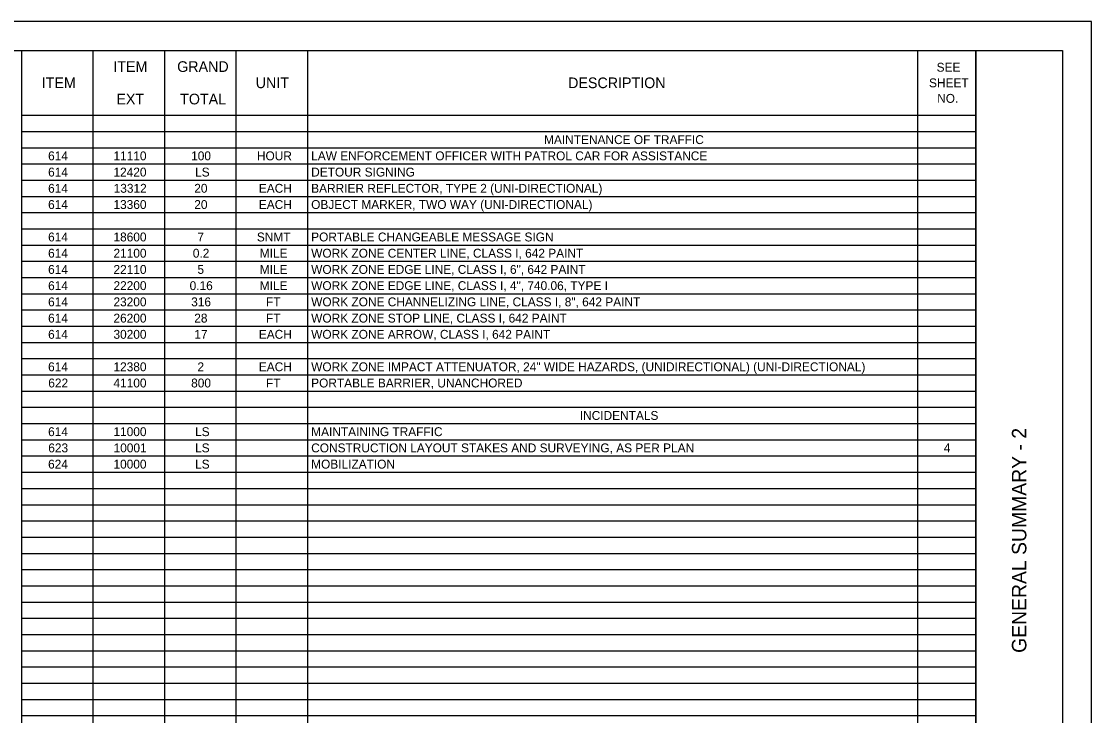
# Model space of a CAD drawing. Extents: x 0 to 34, y 0 to 22.
# Drawn here: x 15.54 to 34, y 10.02 to 22 of the extents above; entities that cross this region are included whole.
import ezdxf

# ---------------------------------------------------------------- set-up
doc = ezdxf.new("R2010")
doc.units = 0
for name, color, linetype in [('SH_Border', 7, 'Continuous'), ('SH_Cut_Line', 7, 'Continuous'), ('SH_Data', 7, 'Continuous'), ('SH_Text', 7, 'Continuous')]:
    doc.layers.add(name, color=color, linetype=linetype)

msp = doc.modelspace()

# ---------------------------------------------------------------- linework, layer by layer
at = {"layer": 'SH_Border'}
msp.add_line((32, 0.5), (32, 21.5), dxfattribs=at)
msp.add_lwpolyline([(1.5, 21.5), (33.5, 21.5), (33.5, 0.5), (1.5, 0.5)], close=True, dxfattribs=at)
at = {"layer": 'SH_Cut_Line'}
msp.add_lwpolyline([(0, 0), (34, 0), (34, 22), (0, 22)], close=True, dxfattribs=at)
at = {"layer": 'SH_Text'}
for p, q in [((15.535, 21.5), (18.003, 21.5)), ((15.535, 21.5), (15.535, 21.22)), ((16.769, 21.5), (16.769, 21.22)), ((18.003, 21.5), (19.237, 21.5)), ((18.003, 21.5), (18.003, 21.22)), ((19.237, 21.5), (32, 21.5)), ((19.237, 21.5), (19.237, 21.22)), ((20.471, 21.5), (20.471, 21.22)), ((30.997, 21.5), (30.997, 21.22)), ((32, 21.5), (32, 21.22)), ((15.535, 21.22), (15.535, 20.94)), ((16.769, 21.22), (16.769, 20.94)), ((18.003, 21.22), (18.003, 20.94)), ((19.237, 21.22), (19.237, 20.94)), ((20.471, 21.22), (20.471, 20.94)), ((30.997, 21.22), (30.997, 20.94)), ((32, 21.22), (32, 20.94)), ((15.535, 20.94), (15.535, 20.66)), ((16.769, 20.94), (16.769, 20.66)), ((18.003, 20.94), (18.003, 20.66)), ((19.237, 20.94), (19.237, 20.66)), ((20.471, 20.94), (20.471, 20.66)), ((30.997, 20.94), (30.997, 20.66)), ((32, 20.94), (32, 20.66)), ((15.535, 20.66), (15.535, 20.38)), ((16.769, 20.66), (16.769, 20.38)), ((18.003, 20.66), (18.003, 20.38)), ((19.237, 20.66), (19.237, 20.38)), ((20.471, 20.66), (20.471, 20.38)), ((30.997, 20.66), (30.997, 20.38)), ((32, 20.66), (32, 20.38)), ((15.535, 20.38), (18.003, 20.38)), ((15.535, 20.38), (15.535, 20.1)), ((16.769, 20.38), (16.769, 20.1)), ((18.003, 20.38), (19.237, 20.38)), ((18.003, 20.38), (18.003, 20.1)), ((19.237, 20.38), (32, 20.38)), ((19.237, 20.38), (19.237, 20.1)), ((20.471, 20.38), (20.471, 20.1)), ((30.997, 20.38), (30.997, 20.1)), ((32, 20.38), (32, 20.1)), ((15.535, 20.1), (18.003, 20.1)), ((15.535, 20.1), (15.535, 18.7)), ((16.769, 20.1), (16.769, 18.7)), ((18.003, 20.1), (19.237, 20.1)), ((18.003, 20.1), (18.003, 18.7)), ((19.237, 20.1), (32, 20.1)), ((19.237, 20.1), (19.237, 18.7)), ((20.471, 20.1), (20.471, 18.7)), ((30.997, 20.1), (30.997, 18.7)), ((32, 20.1), (32, 18.7)), ((15.535, 19.82), (18.003, 19.82)), ((18.003, 19.82), (19.237, 19.82)), ((19.237, 19.82), (32, 19.82)), ((15.535, 19.54), (18.003, 19.54)), ((18.003, 19.54), (19.237, 19.54)), ((19.237, 19.54), (32, 19.54)), ((15.535, 19.26), (18.003, 19.26)), ((18.003, 19.26), (19.237, 19.26)), ((19.237, 19.26), (32, 19.26)), ((15.535, 18.98), (18.003, 18.98)), ((18.003, 18.98), (19.237, 18.98)), ((19.237, 18.98), (32, 18.98)), ((15.535, 18.7), (18.003, 18.7)), ((15.535, 18.7), (15.535, 18.14)), ((16.769, 18.7), (16.769, 18.14)), ((18.003, 18.7), (19.237, 18.7)), ((18.003, 18.7), (18.003, 18.14)), ((19.237, 18.7), (32, 18.7)), ((19.237, 18.7), (19.237, 18.14)), ((20.471, 18.7), (20.471, 18.14)), ((30.997, 18.7), (30.997, 18.14)), ((32, 18.7), (32, 18.14)), ((15.535, 18.42), (18.003, 18.42)), ((18.003, 18.42), (19.237, 18.42)), ((19.237, 18.42), (32, 18.42)), ((15.535, 18.14), (18.003, 18.14)), ((15.535, 18.14), (15.535, 17.86)), ((16.769, 18.14), (16.769, 17.86)), ((18.003, 18.14), (19.237, 18.14)), ((18.003, 18.14), (18.003, 17.86)), ((19.237, 18.14), (32, 18.14)), ((19.237, 18.14), (19.237, 17.86)), ((20.471, 18.14), (20.471, 17.86)), ((30.997, 18.14), (30.997, 17.86)), ((32, 18.14), (32, 17.86)), ((15.535, 17.86), (18.003, 17.86)), ((15.535, 17.86), (15.535, 17.58)), ((16.769, 17.86), (16.769, 17.58)), ((18.003, 17.86), (19.237, 17.86)), ((18.003, 17.86), (18.003, 17.58)), ((19.237, 17.86), (32, 17.86)), ((19.237, 17.86), (19.237, 17.58)), ((20.471, 17.86), (20.471, 17.58)), ((30.997, 17.86), (30.997, 17.58)), ((32, 17.86), (32, 17.58)), ((15.535, 17.58), (18.003, 17.58)), ((15.535, 17.58), (15.535, 17.3)), ((16.769, 17.58), (16.769, 17.3)), ((18.003, 17.58), (19.237, 17.58)), ((18.003, 17.58), (18.003, 17.3)), ((19.237, 17.58), (32, 17.58)), ((19.237, 17.58), (19.237, 17.3)), ((20.471, 17.58), (20.471, 17.3)), ((30.997, 17.58), (30.997, 17.3)), ((32, 17.58), (32, 17.3)), ((15.535, 17.3), (18.003, 17.3)), ((15.535, 17.3), (15.535, 17.02)), ((16.769, 17.3), (16.769, 17.02)), ((18.003, 17.3), (19.237, 17.3)), ((18.003, 17.3), (18.003, 17.02)), ((19.237, 17.3), (32, 17.3)), ((19.237, 17.3), (19.237, 17.02)), ((20.471, 17.3), (20.471, 17.02)), ((30.997, 17.3), (30.997, 17.02)), ((32, 17.3), (32, 17.02)), ((15.535, 17.02), (18.003, 17.02)), ((15.535, 17.02), (15.535, 16.74)), ((16.769, 17.02), (16.769, 16.74)), ((18.003, 17.02), (19.237, 17.02)), ((18.003, 17.02), (18.003, 16.74)), ((19.237, 17.02), (32, 17.02)), ((19.237, 17.02), (19.237, 16.74)), ((20.471, 17.02), (20.471, 16.74)), ((30.997, 17.02), (30.997, 16.74)), ((32, 17.02), (32, 16.74)), ((15.535, 16.74), (18.003, 16.74)), ((15.535, 16.74), (15.535, 16.18)), ((16.769, 16.74), (16.769, 16.18)), ((18.003, 16.74), (19.237, 16.74)), ((18.003, 16.74), (18.003, 16.18)), ((19.237, 16.74), (32, 16.74)), ((19.237, 16.74), (19.237, 16.18)), ((20.471, 16.74), (20.471, 16.18)), ((30.997, 16.74), (30.997, 16.18)), ((32, 16.74), (32, 16.18)), ((15.535, 16.46), (18.003, 16.46)), ((18.003, 16.46), (19.237, 16.46)), ((19.237, 16.46), (32, 16.46)), ((15.535, 16.18), (18.003, 16.18)), ((15.535, 16.18), (15.535, 15.9)), ((16.769, 16.18), (16.769, 15.9)), ((18.003, 16.18), (19.237, 16.18)), ((18.003, 16.18), (18.003, 15.9)), ((19.237, 16.18), (32, 16.18)), ((19.237, 16.18), (19.237, 15.9)), ((20.471, 16.18), (20.471, 15.9)), ((30.997, 16.18), (30.997, 15.9)), ((32, 16.18), (32, 15.9)), ((15.535, 15.9), (18.003, 15.9)), ((15.535, 15.9), (15.535, 15.62)), ((16.769, 15.9), (16.769, 15.62)), ((18.003, 15.9), (19.237, 15.9)), ((18.003, 15.9), (18.003, 15.62)), ((19.237, 15.9), (32, 15.9)), ((19.237, 15.9), (19.237, 15.62)), ((20.471, 15.9), (20.471, 15.62)), ((30.997, 15.9), (30.997, 15.62)), ((32, 15.9), (32, 15.62)), ((15.535, 15.62), (18.003, 15.62)), ((15.535, 15.62), (15.535, 15.34)), ((16.769, 15.62), (16.769, 15.34)), ((18.003, 15.62), (19.237, 15.62)), ((18.003, 15.62), (18.003, 15.34)), ((19.237, 15.62), (32, 15.62)), ((19.237, 15.62), (19.237, 15.34)), ((20.471, 15.62), (20.471, 15.34)), ((30.997, 15.62), (30.997, 15.34)), ((32, 15.62), (32, 15.34)), ((15.535, 15.34), (18.003, 15.34)), ((15.535, 15.34), (15.535, 14.78)), ((16.769, 15.34), (16.769, 14.78)), ((18.003, 15.34), (19.237, 15.34)), ((18.003, 15.34), (18.003, 14.78)), ((19.237, 15.34), (32, 15.34)), ((19.237, 15.34), (19.237, 14.78)), ((20.471, 15.34), (20.471, 14.78)), ((30.997, 15.34), (30.997, 14.78)), ((32, 15.34), (32, 14.78)), ((15.535, 15.06), (18.003, 15.06)), ((18.003, 15.06), (19.237, 15.06)), ((19.237, 15.06), (32, 15.06)), ((15.535, 14.78), (18.003, 14.78)), ((15.535, 14.78), (15.535, 14.5)), ((16.769, 14.78), (16.769, 14.5)), ((18.003, 14.78), (19.237, 14.78)), ((18.003, 14.78), (18.003, 14.5)), ((19.237, 14.78), (32, 14.78)), ((19.237, 14.78), (19.237, 14.5)), ((20.471, 14.78), (20.471, 14.5)), ((30.997, 14.78), (30.997, 14.5)), ((32, 14.78), (32, 14.5)), ((15.535, 14.5), (18.003, 14.5)), ((15.535, 14.5), (15.535, 14.22)), ((16.769, 14.5), (16.769, 14.22)), ((18.003, 14.5), (19.237, 14.5)), ((18.003, 14.5), (18.003, 14.22)), ((19.237, 14.5), (32, 14.5)), ((19.237, 14.5), (19.237, 14.22)), ((20.471, 14.5), (20.471, 14.22)), ((30.997, 14.5), (30.997, 14.22)), ((32, 14.5), (32, 14.22)), ((15.535, 14.22), (18.003, 14.22)), ((15.535, 14.22), (15.535, 13.94)), ((16.769, 14.22), (16.769, 13.94)), ((18.003, 14.22), (19.237, 14.22)), ((18.003, 14.22), (18.003, 13.94)), ((19.237, 14.22), (32, 14.22)), ((19.237, 14.22), (19.237, 13.94)), ((20.471, 14.22), (20.471, 13.94)), ((30.997, 14.22), (30.997, 13.94)), ((32, 14.22), (32, 13.94)), ((15.535, 13.94), (18.003, 13.94)), ((15.535, 13.94), (15.535, 11.7)), ((16.769, 13.94), (16.769, 11.7)), ((18.003, 13.94), (19.237, 13.94)), ((18.003, 13.94), (18.003, 11.7)), ((19.237, 13.94), (32, 13.94)), ((19.237, 13.94), (19.237, 11.7)), ((20.471, 13.94), (20.471, 11.7)), ((30.997, 13.94), (30.997, 11.7)), ((32, 13.94), (32, 11.7)), ((15.535, 13.66), (18.003, 13.66)), ((18.003, 13.66), (19.237, 13.66)), ((19.237, 13.66), (32, 13.66)), ((15.535, 13.38), (18.003, 13.38)), ((18.003, 13.38), (19.237, 13.38)), ((19.237, 13.38), (32, 13.38)), ((15.535, 13.1), (18.003, 13.1)), ((18.003, 13.1), (19.237, 13.1)), ((19.237, 13.1), (32, 13.1)), ((15.535, 12.82), (18.003, 12.82)), ((18.003, 12.82), (19.237, 12.82)), ((19.237, 12.82), (32, 12.82)), ((15.535, 12.54), (18.003, 12.54)), ((18.003, 12.54), (19.237, 12.54)), ((19.237, 12.54), (32, 12.54)), ((15.535, 12.26), (18.003, 12.26)), ((18.003, 12.26), (19.237, 12.26)), ((19.237, 12.26), (32, 12.26)), ((15.535, 11.98), (18.003, 11.98)), ((18.003, 11.98), (19.237, 11.98)), ((19.237, 11.98), (32, 11.98)), ((15.535, 11.7), (18.003, 11.7)), ((15.535, 11.7), (15.535, 11.42)), ((16.769, 11.7), (16.769, 11.42)), ((18.003, 11.7), (19.237, 11.7)), ((18.003, 11.7), (18.003, 11.42)), ((19.237, 11.7), (32, 11.7)), ((19.237, 11.7), (19.237, 11.42)), ((20.471, 11.7), (20.471, 11.42)), ((30.997, 11.7), (30.997, 11.42)), ((32, 11.7), (32, 11.42)), ((15.535, 11.42), (18.003, 11.42)), ((15.535, 11.42), (15.535, 10.3)), ((16.769, 11.42), (16.769, 10.3)), ((18.003, 11.42), (19.237, 11.42)), ((18.003, 11.42), (18.003, 10.3)), ((19.237, 11.42), (32, 11.42)), ((19.237, 11.42), (19.237, 10.3)), ((20.471, 11.42), (20.471, 10.3)), ((30.997, 11.42), (30.997, 10.3)), ((32, 11.42), (32, 10.3)), ((15.535, 11.14), (18.003, 11.14)), ((18.003, 11.14), (19.237, 11.14)), ((19.237, 11.14), (32, 11.14)), ((15.535, 10.86), (18.003, 10.86)), ((18.003, 10.86), (19.237, 10.86)), ((19.237, 10.86), (32, 10.86)), ((15.535, 10.58), (18.003, 10.58)), ((18.003, 10.58), (19.237, 10.58)), ((19.237, 10.58), (32, 10.58)), ((15.535, 10.3), (18.003, 10.3)), ((15.535, 10.3), (15.535, 10.02)), ((16.769, 10.3), (16.769, 10.02)), ((18.003, 10.3), (19.237, 10.3)), ((18.003, 10.3), (18.003, 10.02)), ((19.237, 10.3), (32, 10.3)), ((19.237, 10.3), (19.237, 10.02)), ((20.471, 10.3), (20.471, 10.02)), ((30.997, 10.3), (30.997, 10.02)), ((32, 10.3), (32, 10.02)), ((15.535, 10.02), (18.003, 10.02)), ((15.535, 10.02), (15.535, 9.74)), ((16.769, 10.02), (16.769, 9.74)), ((18.003, 10.02), (19.237, 10.02)), ((18.003, 10.02), (18.003, 9.74)), ((19.237, 10.02), (32, 10.02)), ((19.237, 10.02), (19.237, 9.74)), ((20.471, 10.02), (20.471, 9.74)), ((30.997, 10.02), (30.997, 9.74)), ((32, 10.02), (32, 9.74))]:
    msp.add_line(p, q, dxfattribs=at)

# ---------------------------------------------------------------- texts
at = {"layer": 'SH_Data'}
msp.add_text('GENERAL SUMMARY - 2', height=0.25, rotation=90, dxfattribs=at).set_placement((32.875, 11.102))
at = {"layer": 'SH_Text'}
for s, height, p in [('ITEM', 0.184, (17.121, 21.128)), ('GRAND', 0.184, (18.223, 21.128)), ('SEE ', 0.1533, (31.326, 21.132)), ('ITEM', 0.184, (15.887, 20.848)), ('UNIT', 0.184, (19.578, 20.848)), ('DESCRIPTION', 0.184, (24.968, 20.848)), ('SHEET ', 0.1533, (31.195, 20.863)), ('EXT', 0.184, (17.174, 20.568)), ('TOTAL', 0.184, (18.274, 20.568)), ('NO.', 0.1533, (31.336, 20.595)), ('MAINTENANCE OF TRAFFIC', 0.15333, (24.553, 19.883)), ('614', 0.1533, (15.996, 19.603)), ('11110', 0.1533, (17.124, 19.603)), ('100', 0.1533, (18.464, 19.603)), ('HOUR', 0.1533, (19.599, 19.603)), ('LAW ENFORCEMENT OFFICER WITH PATROL CAR FOR ASSISTANCE', 0.15333, (20.535, 19.603)), ('614', 0.1533, (15.996, 19.323)), ('12420', 0.1533, (17.124, 19.323)), ('LS', 0.1533, (18.532, 19.323)), ('DETOUR SIGNING', 0.15333, (20.535, 19.323)), ('BARRIER REFLECTOR, TYPE 2 (UNI-DIRECTIONAL)', 0.15333, (20.535, 19.043)), ('614', 0.1533, (15.996, 19.043)), ('13312', 0.1533, (17.127, 19.043)), ('20', 0.1533, (18.518, 19.043)), ('EACH', 0.1533, (19.632, 19.043)), ('614', 0.1533, (15.996, 18.763)), ('13360', 0.1533, (17.124, 18.763)), ('20', 0.1533, (18.518, 18.763)), ('EACH', 0.1533, (19.632, 18.763)), ('OBJECT MARKER, TWO WAY (UNI-DIRECTIONAL)', 0.15333, (20.535, 18.763)), ('614', 0.1533, (15.996, 18.203)), ('18600', 0.1533, (17.124, 18.203)), ('7', 0.153, (18.572, 18.203)), ('SNMT', 0.1533, (19.598, 18.203)), ('PORTABLE CHANGEABLE MESSAGE SIGN', 0.15333, (20.535, 18.203)), ('614', 0.1533, (15.996, 17.923)), ('21100', 0.1533, (17.124, 17.923)), ('0.2', 0.1533, (18.493, 17.923)), ('MILE', 0.1533, (19.648, 17.923)), ('WORK ZONE CENTER LINE, CLASS I, 642 PAINT', 0.15333, (20.535, 17.923)), ('614', 0.1533, (15.996, 17.643)), ('22110', 0.1533, (17.124, 17.643)), ('5', 0.153, (18.573, 17.643)), ('MILE', 0.1533, (19.648, 17.643)), ('WORK ZONE EDGE LINE, CLASS I, 6", 642 PAINT', 0.15333, (20.535, 17.643)), ('614', 0.1533, (15.996, 17.363)), ('22200', 0.1533, (17.124, 17.363)), ('0.16', 0.1533, (18.438, 17.363)), ('MILE', 0.1533, (19.648, 17.363)), ('WORK ZONE EDGE LINE, CLASS I, 4", 740.06, TYPE I', 0.15333, (20.535, 17.363)), ('614', 0.1533, (15.996, 17.083)), ('23200', 0.1533, (17.124, 17.083)), ('316', 0.1533, (18.465, 17.083)), ('FT', 0.1533, (19.756, 17.083)), ('WORK ZONE CHANNELIZING LINE, CLASS I, 8", 642 PAINT', 0.15333, (20.535, 17.083)), ('614', 0.1533, (15.996, 16.803)), ('26200', 0.1533, (17.124, 16.803)), ('28', 0.1533, (18.518, 16.803)), ('FT', 0.1533, (19.756, 16.803)), ('WORK ZONE STOP LINE, CLASS I, 642 PAINT', 0.15333, (20.535, 16.803)), ('614', 0.1533, (15.996, 16.523)), ('30200', 0.1533, (17.124, 16.523)), ('17', 0.1533, (18.519, 16.523)), ('EACH', 0.1533, (19.632, 16.523)), ('WORK ZONE ARROW, CLASS I, 642 PAINT', 0.15333, (20.535, 16.523)), ('614', 0.1533, (15.996, 15.963)), ('12380', 0.1533, (17.124, 15.963)), ('2', 0.153, (18.573, 15.963)), ('EACH', 0.1533, (19.632, 15.963)), ('WORK ZONE IMPACT ATTENUATOR, 24" WIDE HAZARDS, (UNIDIRECTIONAL) (UNI-DIRECTIONAL)', 0.15333, (20.535, 15.963)), ('622', 0.1533, (15.999, 15.683)), ('41100', 0.1533, (17.124, 15.683)), ('800', 0.1533, (18.464, 15.683)), ('FT', 0.1533, (19.756, 15.683)), ('PORTABLE BARRIER, UNANCHORED', 0.15333, (20.535, 15.683)), ('INCIDENTALS', 0.15333, (25.17, 15.123)), ('614', 0.1533, (15.996, 14.843)), ('11000', 0.1533, (17.124, 14.843)), ('LS', 0.1533, (18.532, 14.843)), ('MAINTAINING TRAFFIC', 0.15333, (20.535, 14.843)), ('623', 0.1533, (15.999, 14.563)), ('10001', 0.1533, (17.126, 14.563)), ('LS', 0.1533, (18.532, 14.563)), ('CONSTRUCTION LAYOUT STAKES AND SURVEYING, AS PER PLAN', 0.15333, (20.535, 14.563)), ('4', 0.153, (31.449, 14.563)), ('624', 0.1533, (15.996, 14.283)), ('10000', 0.1533, (17.124, 14.283)), ('LS', 0.1533, (18.532, 14.283)), ('MOBILIZATION', 0.15333, (20.535, 14.283))]:
    msp.add_text(s, height=height, dxfattribs=at).set_placement(p)

doc.saveas('drawing.dxf')
